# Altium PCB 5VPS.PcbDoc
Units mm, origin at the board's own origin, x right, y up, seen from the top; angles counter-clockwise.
Board outline 33.7 x 23.2 mm, 2 copper layers (Top Layer, Bottom Layer), stack 1.575 mm thick; 29 components, 18 nets, 69 pads, 4 vias.
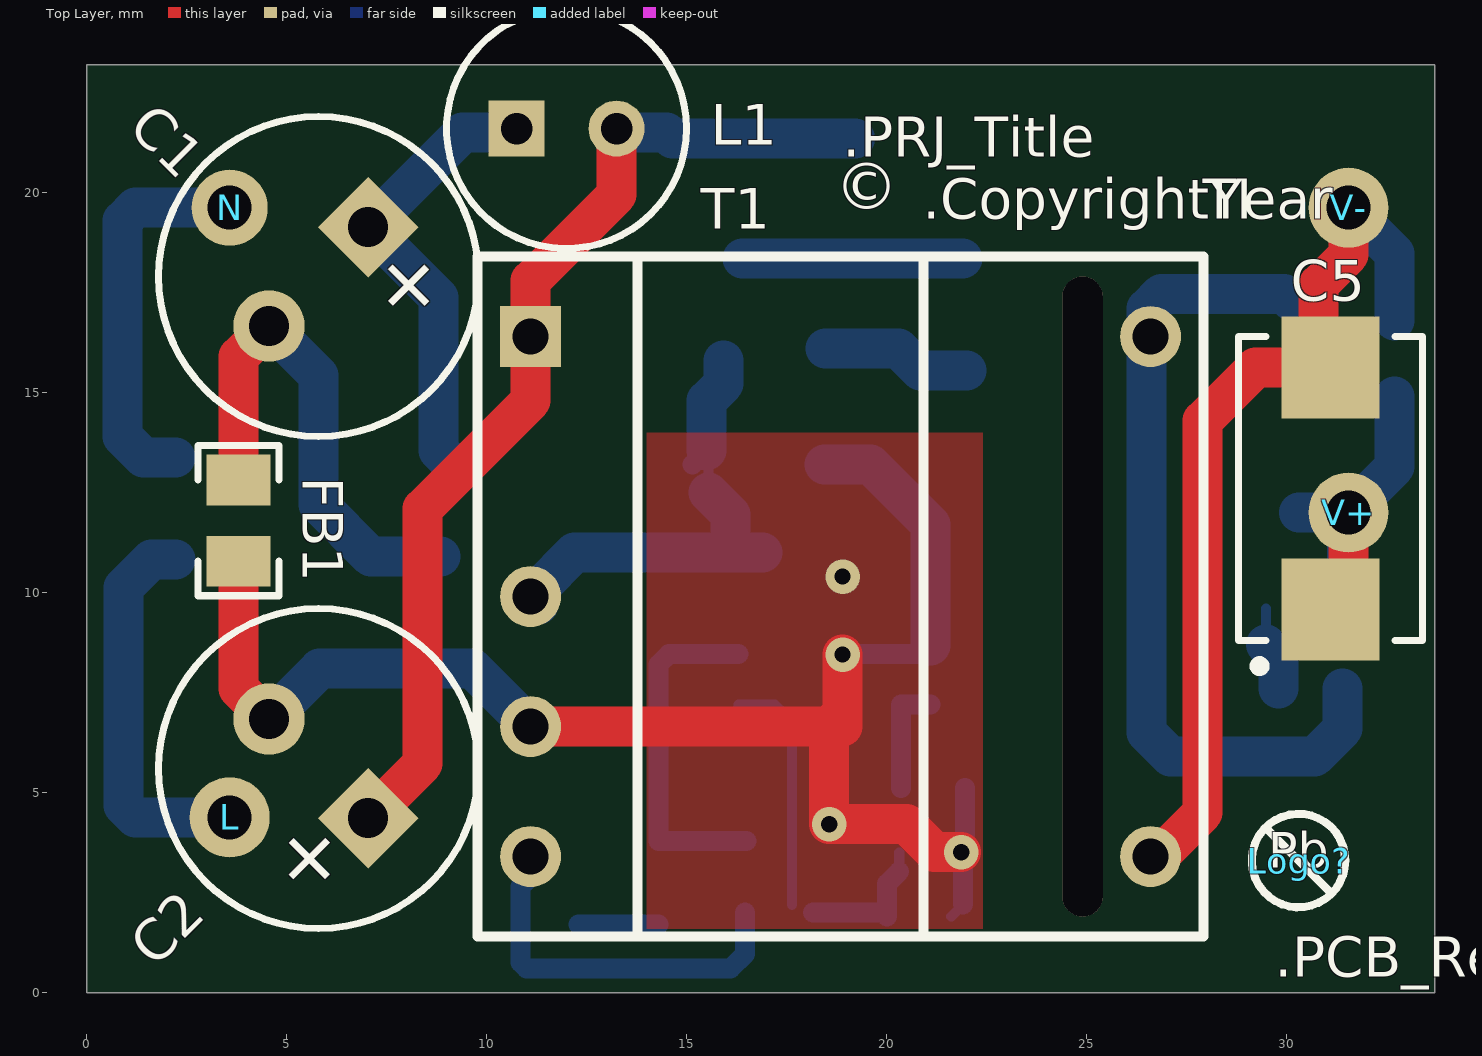
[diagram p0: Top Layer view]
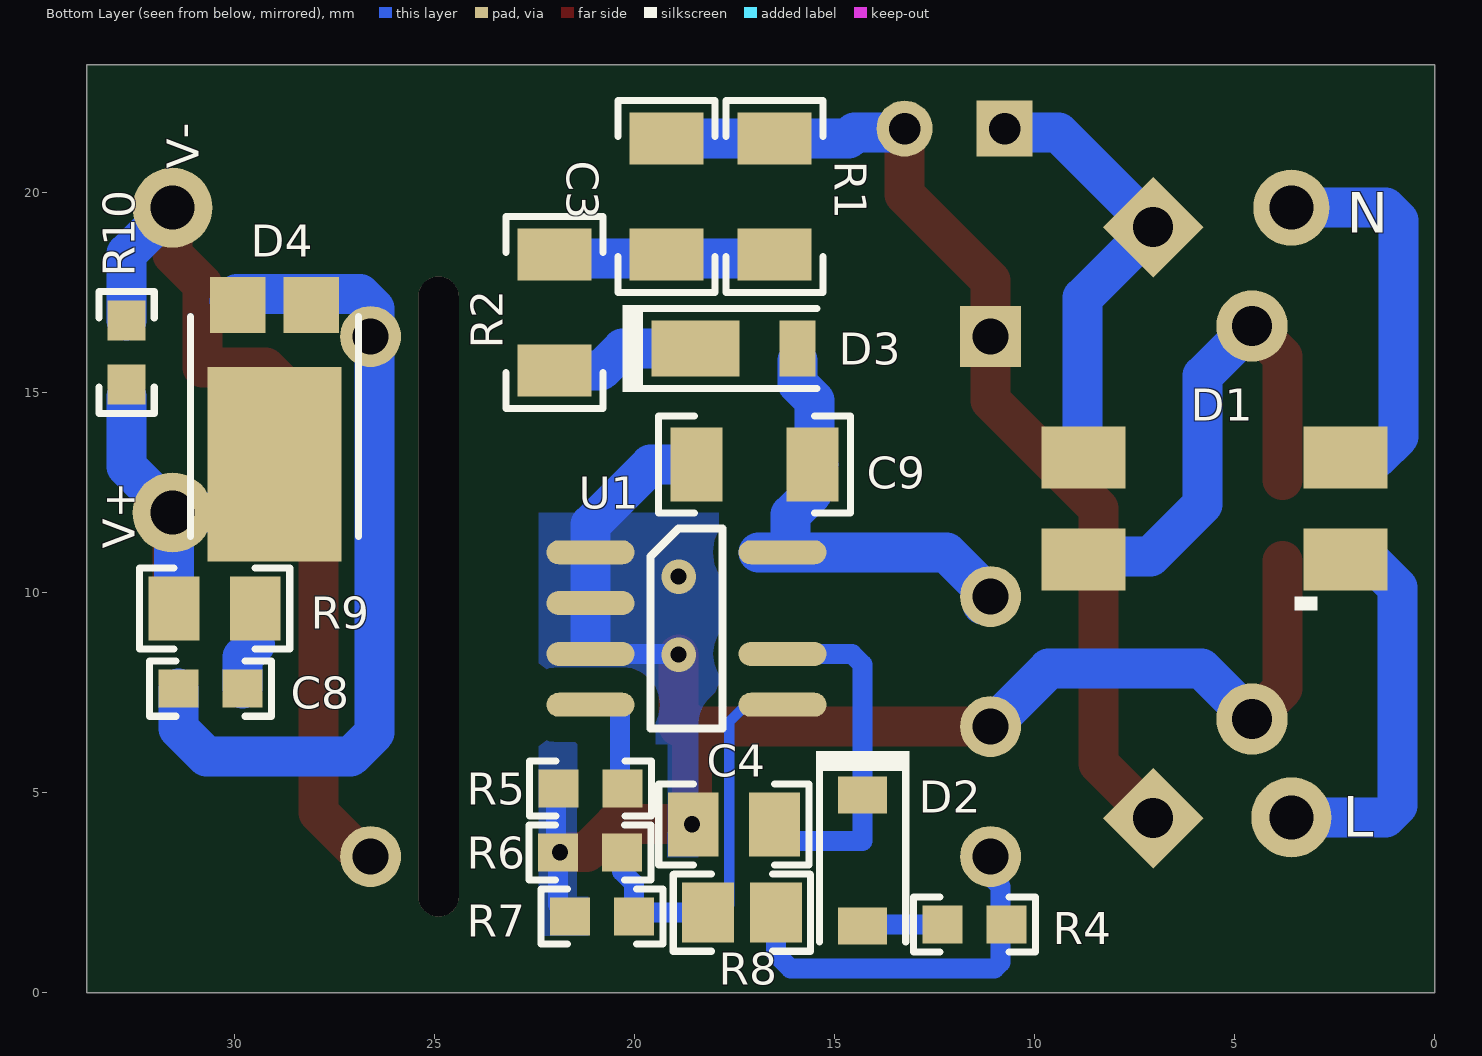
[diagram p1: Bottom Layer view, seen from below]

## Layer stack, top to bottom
Top Solder: solder mask 0.0102, Solder Resist, Dk 3.5
Top Layer: signal copper 0.0356
Dielectric1: core 1.5037, FR-4, Dk 4.8
Bottom Layer: signal copper 0.0356
Bottom Solder: solder mask 0.0102, Solder Resist, Dk 3.5

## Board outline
0,0 33.7,0 33.7,23.2 0,23.2

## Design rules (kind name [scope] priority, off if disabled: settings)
AcuteAngle [All] p1: minimum=4.50000000000000E+0001 checktracksonly=FALSE
AssemblyTestPointUsage [All] p1: valid=2
Clearance Clearance_BoardEdge_MountingHoles [OnCopper and InComponentClass('Mounting Holes') vs IsKeepOut] p1: gap=1.016
Clearance Clearance_BoardEdge_Poly [OnCopper and InPoly vs IsKeepOut] p2: gap=0.635
Clearance Clearance_BoardEdge [OnCopper and Not InComponentClass('Logo') and not InComponentClass('FiducialMark') and not InRegion(1000,500,4000,800) and Not IsKeepout vs IsKeepOut] p3: gap=1.905
Clearance Clearance_Poly [InPolygon] p4: gap=0.635
Clearance [All] p5: gap=0.203
ComponentClearance ComponentClearance_Shunt [InComponentClass('Header') vs InComponentClass('Shunt')] p1: gap=0 collisioncheckmode=3 verticalgap=0 showdistances=FALSE
ComponentClearance ComponentClearance_Logo [InComponentClass('Logo')] p2: gap=1.27 collisioncheckmode=3 verticalgap=0.254 showdistances=FALSE
ComponentClearance ComponentClearance_ScrewToNut [(HasFootprint('NY PMS 440 0025 PH')) vs (HasFootprint('Keystone_1902C'))] p3: gap=0.127 collisioncheckmode=3 verticalgap=0.254 showdistances=FALSE
ComponentClearance ComponentClearance_MountingHoles [InComponentClass('Mounting Holes')] p4: gap=6.35 collisioncheckmode=3 verticalgap=2540 showdistances=FALSE
ComponentClearance ComponentClearance_SmallPassives [HasFootprint('0201*') or HasFootprint('0402*') or HasFootprint('0508') or HasFootprint('0603*') or HasFootprint('0612') or HasFootprint('0805*') or HasFootprint('0815*') or HasFootprint('0830*') or HasFootprint('1206*') or HasFootprint('1210*') or HasFootprint('1808*') or HasFootprint('1812*') or HasFootprint('1825*') or HasFootprint('2010*') or HasFootprint('2220*') or HasFootprint('2225*') or HasFootprint('2512*') or HasFootprint('2728*') or HasFootprint('3518*') vs HasFootprint('0201*') or HasFootprint('0402*') or HasFootprint('0508') or HasFootprint('0603*') or HasFootprint('0612') or HasFootprint('0805*') or HasFootprint('0815*') or HasFootprint('0830*') or HasFootprint('1206*') or HasFootprint('1210*') or HasFootprint('1808*') or HasFootprint('1812*') or HasFootprint('1825*') or HasFootprint('2010*') or HasFootprint('2220*') or HasFootprint('2225*') or HasFootprint('2512*') or HasFootprint('2728*') or HasFootprint('3518*')] p5: gap=0.508 collisioncheckmode=3 verticalgap=0.254 showdistances=FALSE
ComponentClearance ComponentClearance_THtoSMT [IsThruComponent vs IsSMTComponent] p6: gap=2.54 collisioncheckmode=3 verticalgap=0.762 showdistances=FALSE
ComponentClearance ComponentClearance_THtoTH [IsThruComponent vs IsThruComponent] p7: gap=3 collisioncheckmode=3 verticalgap=0.762 showdistances=FALSE
ComponentClearance [All] p8: gap=1.016 collisioncheckmode=3 verticalgap=0.254 showdistances=FALSE
DiffPairsRouting [All] p1: maxlimit=2.54 minlimit=0.254 mostfreqgap=0.254 toplayer_minwidth=0.381 toplayer_maxwidth=0.381 toplayer_prefwidth=0.381 bottomlayer_minwidth=0.381 bottomlayer_maxwidth=0.381 bottomlayer_prefwidth=0.381 maxuncoupledlength=25.4
FabricationTestPointUsage TestPointUsage [All] p1: valid=2 allowmultiple=FALSE
FabricationTestpoint Testpoint [All] p1: side=3 testpointundercomponent=TRUE minsize=1.016 maxsize=2.54 preferedsize=1.524 minholesize=0 maxholesize=1.016 preferedholesize=0.813 testpointgrid=0.025 allowsidetop=TRUE allowsidebottom=TRUE usegrid=TRUE gridtolerance=0
FanoutControl Fanout_LCC [IsLCC] p1: bgadir=Out bgaviamode=Centered fanoutstyle=Auto fanoutdirection=Alternating viagrid=0.025 // Fanout_LCC (Default Rule)
FanoutControl Fanout_BGA [IsBGA] p2: bgadir=Out bgaviamode=Centered fanoutstyle=Auto fanoutdirection=Alternating viagrid=0.025 // Fanout_BGA (Default Rule)
FanoutControl Fanout_Default [All] p4: bgadir=Out bgaviamode=Centered fanoutstyle=Auto fanoutdirection=Alternating viagrid=0.025 // Fanout_Default (Default Rule)
FanoutControl Fanout_Small [(CompPinCount < 5)] p5: bgadir=Out bgaviamode=Centered fanoutstyle=Auto fanoutdirection=OutThenIn viagrid=0.025 // Fanout_Small (Default Rule)
HoleSize [All] p1: absolutevalues=TRUE maxlimit=6.375 minlimit=0.203 maxpercent=80.000 minpercent=20.000
MinimumAnnularRing MinimumAnnularRing_ThermalPadVias [IsVia and InAnyComponent] p1: minimumring=0.15
MinimumAnnularRing [All] p2: minimumring=0.229
MinimumSolderMaskSliver MinimumSolderMaskSliver_Logo [InComponentClass('Logo') vs InComponentClass('Logo')] p1: minsoldermaskwidth=0.018
MinimumSolderMaskSliver [All] p2: minsoldermaskwidth=0.1
PlaneClearance [All] p1: clearance=0.127
PlaneConnect [All] p1: planeconnectstyle=Direct reliefexpansion=0.254 reliefentries=4 reliefconductorwidth=0.254 reliefairgap=0.254
PolygonConnect [All] p1: connectstyle=Direct reliefconductorwidth=0.254 reliefentries=4 polygonreliefangle="90 Angle" airgapwidth=0.254
RoutingVias ThermalPadVias [IsVia and InAnyComponent] p1: holewidth=0.2 width=0.5 viastyle="Through Hole" minholewidth=0.2 minwidth=0.5 maxholewidth=0.33 maxwidth=0.6
RoutingVias [All] p2: holewidth=0.406 width=0.864 viastyle="Through Hole" minholewidth=0.2 minwidth=0.66 maxholewidth=1.016 maxwidth=1.651
SMDToCorner [All] p1: distance=30000
SilkToSilkClearance [All] p1: silktosilkclearance=0.127
SilkToSolderMaskClearance SilkscreenOverComponentPads [IsPad] p1: minsilkscreentomaskgap=0.127 clearancetoexposedcopper=TRUE
SolderMaskExpansion [All] p1: expansion=0.05
UnpouredPolygon [All] p1: allowunpoured=FALSE
Width [All] p1: maxlimit=2.54 minlimit=0.152 preferedwidth=0.254 checkconnectedcopper=TRUE
14 further rules are at their usual default settings.

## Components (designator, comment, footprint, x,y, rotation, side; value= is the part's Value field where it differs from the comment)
C1 "400AX8.2M8X16" CAPPRD350W60D800H1100 5.8,17.9 r225 top
C2 "400AX8.2M8X16" CAPPRD350W60D800H1100 5.8,5.6 r135 top
C3 "GRM31A7U2J221JW31D" 1206 19.2,19.9 r270 bottom
C4 "GRM21BC81E475KA12L" 0805_HV 17.516,4.2 r0 bottom
C5 "TPSE477K010R0045" 7343-43 31.1,12.6 r90 top
C8 "C1608C0G1H102J" 0603 30.6,7.6 r0 bottom
C9 "GRM31A7U3A330JW31D" 1206 17,13.2 r0 bottom
D1 "MB6S" TO-269AA 5.5,12.1 r0 bottom
D2 "BAV21W-7-F" SOD-123 14.3,3.3 r270 bottom
D3 "DFLR1600" powerDI123 17.2,16.1 r180 bottom
D4 "PDS1040L-13" PowerDI5 29,15.2 r270 bottom
FB1 "MPZ2012S601A" 0805_HV 3.8,11.8 r270 top
L "KEY1050-ND" TESTPOINT#1 2.7,19.3 r90 top
L1 "470uH" IND_WE-TI_XS 12,21.6 r0 top
Logo? "Pb-Free Symbol" Pb-Free_Overlay_Small 30.3,3.3 r0 top
N "KEY1050-ND" TESTPOINT#2 2.7,3.4 r90 top
R1 "RC1206FR-07300KL" 1206 16.5,19.9 r270 bottom
R2 "RC1206FR-07300RL" 1206 22,17 r90 bottom
R4 "CRCW060322R0JNEA" 0603 11.5,1.7 r180 bottom
R5 "RC0603JR-071K3L" 0603 21.1,5.1 r180 bottom
R6 "CRCW060336K0JNEA" 0603 21.116,3.5 r180 bottom
R7 "CRCW0603910KJNEA" 0603 20.816,1.9 r180 bottom
R8 "CRCW080562K0JNEA" 0805 17.316,2 r180 bottom
R9 "ERJ-6GEYJ150V" 0805_HV 30.5,9.6 r0 bottom
R10 "RC0603JR-073K9L" 0603 32.7,16 r270 bottom
T1 "TF-1613(EE-16)" TF-1613(EE-16) 18.85,9.9 r0 top
U1 "UCC28910D" D0007A_N 18.7,9.1 r180 bottom
V+ "KEY1050-ND" TESTPOINT#3 32.4,10.4 r0 top
V- "KEY1050-ND" TESTPOINT#4 31.8,19.4 r0 top

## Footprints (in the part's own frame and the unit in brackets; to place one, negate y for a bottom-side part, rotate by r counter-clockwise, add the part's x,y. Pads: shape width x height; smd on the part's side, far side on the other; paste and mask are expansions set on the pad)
0603 [mm] "0603 from SM-752 data"
  rect 1x0.95 smd: 1(-0.8,0) 2(0.8,0)
  silkscreen extent -1.52,-0.69 1.52,0.69, body extent -0.87,-0.47 0.87,0.47, height 0.85
0805 [mm] "0805 from SM-752 data"
  rect 1.3x1.5 smd: 1(-0.85,0) 2(0.85,0)
  silkscreen extent -1.72,-0.97 1.72,0.97, body extent -1.1,-0.72 1.1,0.72, height 1.1
0805_HV [mil] "0805 with 30mil clearance between pads"
  rect 50x63 smd: 1(-40,0) 2(40,0)
  silkscreen extent -74,-40 74,40, body extent -43,-29 43,29, height 43
1206 [mm] "1206 from SM-752 data"
  rect 1.3x1.85 smd: 1(-1.45,0) 2(1.45,0)
  silkscreen extent -2.4,-1.21 2.4,1.21, body extent -1.7,-0.9 1.7,0.9, height 1.35
7343-43 [mm] "Medium density IPC based on Kemet T495 series"
  rect 2.55x2.45 smd: 1(-3.025,0) 2(3.025,0)
  silkscreen extent -4.56,-2.3 3.8,2.3, body extent -3.8,-2.3 3.8,2.3, height 4.3
CAPPRD350W60D800H1100 [mm] "Capacitor, Alum, 8x11mm"
  rect 1.78x1.78 hole 1: 1(-1.75,0)
  round 1.78 hole 1: 2(1.75,0)
  silkscreen extent -4,-4 4,4, body extent -4.03,-4.03 4.03,4.02, height 11.79
D0007A_N [mm] "SOIC, 7-Leads, Body 4.9x3.9mm, Pitch 1.27mm, IPC Medium Density"
  oval 2.2x0.6 smd: 1(-2.4,1.905) 2(-2.4,0.635) 3(-2.4,-0.635) 4(-2.4,-1.905) 5(2.4,-1.905) 6(2.4,-0.635) 8(2.4,1.905)
  silkscreen extent -0.9,-2.5 0.9,2.5, body extent -3,-2.5 3,2.5, height 1.54
IND_WE-TI_XS [mm] "Wurth WE-TI 5075"
  rect 1.4x1.4 hole 0.787: 1(-1.25,0)
  round 1.4 hole 0.787: 2(1.25,0)
  silkscreen extent -3,-3 3,3, body extent -3.01,-3.01 3.01,3.01, height 8.5
Pb-Free_Overlay_Small [mm]
  silkscreen extent -1.16,-1.17 1.17,1.17
PowerDI5 [mm] "Diodes Inc recommended land pattern, ap02001.pdf rev 60"
  rect 1.4x1.39 smd: 1(-1.991,0.92) 2(-1.991,-0.92)
  rect 4.86x3.36 smd: 3(1.991,0)
  silkscreen extent -1.7,-2.1 3.8,2.1, body extent -2.27,-2.02 4.33,2.03, height 1.17
powerDI123 [mm] "Diodes Inc recommended land pattern, document number DS30628 Rev. 6-2"
  rect 2.2x1.4 smd: 1(-1.275,0)
  rect 0.9x1.4 smd: 2(1.275,0)
  silkscreen extent -3.1,-1.09 1.76,1.09, body extent -2.37,-0.96 1.53,0.97, height 1
SOD-123 [mm] "On Semi recommended land pattern"
  rect 0.915x1.22 smd: 1(-1.637,0) 2(1.637,0)
  silkscreen extent -2.74,-1.17 2.03,1.17, body extent -1.93,-0.9 1.93,0.9, height 1.35
TESTPOINT#1 [mm]
  round 2 hole 1.1: 1(-14.92,-0.88)
TESTPOINT#2 [mm]
  round 1.9 hole 1.1: 1(16.22,-0.88)
TESTPOINT#3 [mm]
  round 2 hole 1.1: 1(-0.85,1.6)
TESTPOINT#4 [mm]
  round 2 hole 1.1: 1(-0.25,0.22)
TF-1613(EE-16) [mm]
  rect 1.524x1.524 hole 0.9: 1(-7.75,6.5)
  round 0 all layers, no hole: 2(-7.75,3.25) 7(7.75,-3.25) 8(7.75,0) 9(7.75,3.25)
  round 1.524 hole 0.9: 3(-7.75,0) 4(-7.75,-3.25) 5(-7.75,-6.5) 6(7.75,-6.5) 10(7.75,6.5)
  silkscreen extent -9.08,-8.5 9.08,8.5, body extent -9.1,-8.5 9,8.5, height 10.96
TO-269AA [mm] "Fairchild"
  rect 2.1x1.55 smd: 1(-3.28,1.27) 2(-3.28,-1.27) 3(3.28,-1.27) 4(3.28,1.27)
  silkscreen extent -2.58,2.2 -2,2.55, body extent -3.5,-2.47 3.5,2.47, height 2.91

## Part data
C1 C2: library part 400AX6R8M8x11, "CAP, AL, 6.8uF, 400V, +/-20%, TH"
C3: "CAP, CERM, 220pF, 630V, +/-5%, U2J, 1206"
C4: "CAP, CERM, 4.7uF, 25V, +/-10%, X6S, 0805"
C5: "CAP, TA, 470uF, 10V, +/-10%, 0.045 ohm, SMD"
C8: "CAP, CERM, 1000pF, 50V, +/-5%, C0G/NP0, 0603"
C9: library part GRM31A7U3A331JW31D, "CAP, CERM, 33pF, 1000V, +/-5%, U2J, 1206"
D1: library part MB1S, "Diode, Switching-Bridge, 100V, 0.5A, SOIC-4"
D2: "Diode, Switching, 200V, 0.2A, SOD-123"
D3: library part DFLU1400-7, "Diode, Superfast Rectifier, 600V, 1A, PowerDI123"
D4: "Diode, Schottky, 40V, 10A, PowerDI5"
FB1: "2A Ferrite Bead, 600 ohm @ 100MHz, SMD"
L N V+ V-: library part TESTPOINT, "TEST POINT.  No entry in BOM."
L1: library part 7447462471, "Inductor, Unshielded Drum Core, Ferrite, 470uH, 0.35A, 1.58 ohm, TH"
Logo?: library part Pb-Free
R1: "RES, 300k ohm, 1%, 0.25W, 1206"
R2: "RES, 300 ohm, 1%, 0.25W, 1206"
R4: "RES, 22 ohm, 5%, 0.1W, 0603"
R5: "RES, 1.3k ohm, 5%, 0.1W, 0603"
R6: "RES, 36k ohm, 5%, 0.1W, 0603"
R7: "RES, 910k ohm, 5%, 0.1W, 0603"
R8: "RES, 62k ohm, 5%, 0.125W, 0805"
R9: "RES, 15 ohm, 5%, 0.125W, 0805"
R10: "RES, 3.9k ohm, 5%, 0.1W, 0603"
U1: "LOW STAND-BY POWER, CV / CC PWM HV SWITCHER WITH PRIMARY SIDE REGULATION, D0007A"

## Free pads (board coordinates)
  oval 1x16 hole 1 slot 16 at 90 deg unplated: 0(24.9,9.9)

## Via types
v1: diameter 0.864, hole 0.406, Top Layer to Bottom Layer, 4 vias

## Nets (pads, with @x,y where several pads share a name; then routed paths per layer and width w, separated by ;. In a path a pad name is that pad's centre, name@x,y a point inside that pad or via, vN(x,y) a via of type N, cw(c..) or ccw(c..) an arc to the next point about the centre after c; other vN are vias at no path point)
GND: C2.2 C4.2 C9.2 FB1.2 R5.1 R6.1 R7.1 T1.4 U1.1 U1.2 U1.3 | length 39.5
  Top Layer w1: FB1.2 3.8,7.6 C2.2 ; T1.4@11.6,6.65 18.55,6.65 ; 18.8,6.9 18.566,6.666 18.566,6.65 ; v1(18.9,8.45) 18.9,6.65 18.566,6.65 ; v1(21.866,3.51) 21.2,3.51 20.5,4.21 v1(18.566,4.21) 18.566,6.65
  Bottom Layer w0.254: C4.2@18.336,4.396 C4.2 18.556,4.2 v1(18.566,4.21) ; R7.1 R7.1@21.916,2.2
  Bottom Layer w0.5: v1@18.915,8.465 U1.3 ; R7.1@21.916,2.2 R6.1 ; R6.1@21.966,3.55 R5.1@21.966,5.11
  Bottom Layer w1: C2.2 5.825,8.1 9.65,8.1 T1.4 ; C9.2 19.6,13.2 21.1,11.7 U1.2 U1.3@21.1,8.67
  other v1: 18.9,10.4
NetC1_1: C1.1 D1.3 L1.1 | length 11.3
  Bottom Layer w1: D1.3@8.98,13.37 8.8,13.55 8.8,17.375 C1.1 9.4,21.5 L1.1@10.75,21.5
NetC1_2: C1.2 D1.4 FB1.1 | length 12.7
  Top Layer w1: FB1.1 3.8,15.9 C1.2
  Bottom Layer w1: C1.2 5.8,15.425 5.8,12.207 7.107,10.9 D1.4@8.85,10.9
NetC2_1: C2.1 C3.1 L1.2 R1.1 T1.1 | length 25.7
  Top Layer w1: C2.1 8.4,5.725 8.4,12.1 11.1,14.8 11.1,17.8 13.25,19.95 L1.2@13.25,21.5
  Bottom Layer w1: L1.2@13.25,21.5 14.5,21.5 14.65,21.35 C3.1@19.21,21.35
NetC3_2: C3.2 R1.2 R2.2 | length 5.5
  Bottom Layer w1: R1.2@16.4,18.35 R2.2@21.9,18.35
NetC4_1: C4.1 D2.1 U1.6 | length 8.7
  Bottom Layer w0.5: U1.6 14.565,8.465 14.3,8.2 14.3,3.79 C4.1@16.5,3.79
NetC5_1: C5.1 D4.3 R9.2 R10.2 V+.1 | length 8.7
  Top Layer w1: C5.1@31.55,10.325 V+.1
  Bottom Layer w1: D4.3@30.309,12 V+.1 32.7,13.15 R10.2@32.7,14.9 ; R9.2 V+.1@31.516,11.966
NetC5_2: C5.2 R10.1 T1.6 V-.1 | length 22.5
  Top Layer w1: T1.6@26.7,3.3 27.9,4.5 27.9,14.3 29.225,15.625 30.8,15.625 30.8,17.7 31.55,18.45 V-.1
  Bottom Layer w1: V-.1 32.7,18.47 R10.1
NetC8_1: C8.1 R9.1 | length 2.1
  Bottom Layer w0.254: 29.484,8.7 R9.1
  Bottom Layer w1: 29.484,8.7 29.8,8.384 C8.1
NetC8_2: C8.2 D4.1 D4.2 T1.10 | length 20.9
  Bottom Layer w1: D4.2@30.12,17.291 29.942,17.469 26.869,17.469 26.5,17.1 26.5,6.5 27.1,5.9 30.7,5.9 31.4,6.6 C8.2
NetC9_1: C9.1 D3.2 T1.3 U1.8 | length 11.8
  Bottom Layer w0.254: C9.1@15.55,12.5 C9.1
  Bottom Layer w0.5: C9.1@15.15,13.2 C9.1@15.5,13.55
  Bottom Layer w1: T1.3@11.3,9.7 11.3,10.1 12.205,11.005 U1.8@16.9,11.005 ; C9.1@15.5,13.55 15.5,14.8 15.925,15.225 D3.2@15.925,15.8 ; C9.1@15.55,12.5 16.1,11.95 16.1,11.205 U1.8
NetD1_1: D1.1 L.1 | length 9.8
  Bottom Layer w1: D1.1 1.63,10.83 0.92,10.12 0.92,4.68 1.22,4.38 L.1
NetD1_2: D1.2 N.1 | length 9.8
  Bottom Layer w1: D1.2 1.43,13.37 0.9,13.9 0.9,19.3 1.22,19.62 N.1
NetD2_2: D2.2 R4.1 | length 2
  Bottom Layer w0.5: R4.1@12.3,1.7 D2.2@14.3,1.7
NetD3_1: D3.1 R2.1 | length 3.8
  Bottom Layer w1: D3.1 20.3,16.1 20.85,15.55 R2.1
NetR4_2: R4.2 R8.2 T1.5 | length 9.8
  Bottom Layer w0.5: T1.5@11.6,3.4 10.853,2.653 10.853,2.105 10.85,2.102 10.85,0.75 11,0.6 16.1,0.6 16.466,0.966 R8.2
NetR5_2: R5.2 U1.4 | length 2.8
  Bottom Layer w0.5: R5.2@20.366,5.11 20.366,7.205 21.09,7.205 U1.4
NetR6_2: R6.2 R7.2 R8.1 U1.5 | length 9.7
  Bottom Layer w0.254: U1.5 17.205,7.195 17.633,6.767 R8.1@17.633,2.189 ; R7.2@19.916,2 R7.2 ; R6.2@20.316,3.025 R6.2
  Bottom Layer w0.5: R8.1 R7.2@19.916,2 ; R7.2 20.016,2.725 R6.2@20.316,3.025
pads on no net: T1.2 T1.7 T1.8 T1.9

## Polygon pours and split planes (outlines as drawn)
GND on Top Layer "Top Layer-No Net" (solid, remove dead copper, pour order 2): 14,14 22.4,14 22.4,1.6 14,1.6 14,14
GND on Bottom Layer "Bottom Layer-No Net" (solid, remove dead copper, pour order 4): 17.9,12 22.4,12 22.4,1.426 17.9,1.426 17.9,12

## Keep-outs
Keep-Out Layer:
  text ".Layer_Name" at 14.656,-21.806 h1.52

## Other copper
Top Layer:
  text ".PRJ_Number" at 39.9,17.03 h1
  text ".Layer_Name" at 14.656,-21.806 h1.52
Bottom Layer:
  text ".PRJ_Number" at 39.9,15.157 h1
  text ".Layer_Name" at 14.656,-21.806 h1.52

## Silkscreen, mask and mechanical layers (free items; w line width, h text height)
Top Overlay:
  text ".PRJ_Number" at 39.9,22.65 h1
  text ".PRJ_Title" at 18.9,20.9 h1
  text ".CopyrightYear" at 20.9,19.35 h1
  text "TI" at 27.91,19.35 h1
  text "©" at 18.7,19.2 h2
  text ".PCB_Rev" at 29.7,0.4 h1
  text ".Layer_Name" at 14.656,-21.806 h1.52
Bottom Overlay:
  text ".PRJ_Number" at 39.9,9.537 h1
  text ".Layer_Name" at 14.656,-21.806 h1.52
Top Paste:
  text ".PRJ_Number" at 39.9,18.904 h1
  text ".Layer_Name" at 14.656,-21.806 h1.52
Bottom Paste:
  text ".PRJ_Number" at 39.9,13.284 h1
  text ".Layer_Name" at 14.656,-21.806 h1.52
Top Solder:
  text ".PRJ_Number" at 39.9,20.777 h1
  text ".Layer_Name" at 14.656,-21.806 h1.52
  text ".Layer_Name" at 14.656,-21.806 h1.52
Bottom Solder:
  text ".PRJ_Number" at 39.9,11.411 h1
  text ".Layer_Name" at 14.656,-21.806 h1.52
Drill Guide:
  text ".PRJ_Number" at 39.9,0.171 h1
  text ".Layer_Name" at 14.656,-21.806 h1.52
M1 Board Outline:
  the board outline again, w0.254
  text ".PRJ_Number" at 39.9,7.664 h1
  text ".Layer_Name" at 14.656,-21.806 h1.52
M2 Board Dimensions:
  rectangle: -0.013,-7.252 3.162,-4.077
  rectangle: 3.162,-10.427 12.687,-7.252
  lines w0.178: -0.013,-7.252 25.387,-7.252 ; 3.162,-10.427 3.162,-4.077 ; 6.337,-10.427 6.337,-4.077 ; 12.687,-10.427 12.687,-4.077 ; 19.037,-10.427 19.037,-4.077 ; -0.013,-10.427 25.387,-10.427 25.387,-4.077 -0.013,-4.077 -0.013,-10.427
  lines w0.254: -0.013,-12.078 -0.013,-11.57 ; 1.511,-12.332 -0.013,-11.824 ; 1.511,-11.316 -0.013,-11.824 ; 6.187,-11.824 -0.013,-11.824 ; 19.188,-11.824 25.387,-11.824 ; 23.863,-12.332 25.387,-11.824 ; 23.863,-11.316 25.387,-11.824 ; 25.387,-12.078 25.387,-11.57
  text ".PRJ_Number" at 39.9,5.791 h1
  text "25.4 (mm)" at 6.441,-12.738 h1.52
  text ".Layer_Name" at 14.656,-21.806 h1.52
M3 3D STEP Top:
  text ".Layer_Name" at 14.656,-21.806 h1.52
M4 3D STEP Bottom:
  text ".Layer_Name" at 14.656,-21.806 h1.52
M5 Assembly Top:
  lines w0.254: -7.417,-23.626 160.223,-23.626 ; -7.417,-18.462 160.274,-18.462 ; -7.417,-13.297 -7.417,-28.791 94.31,-28.791 160.274,-28.791 160.274,-13.297 -7.404,-13.297 -7.404,-28.791 32.614,-28.791 ; 55.194,-28.791 55.194,-13.297 ; 87.376,-18.462 87.376,-13.297 ; 108.712,-18.462 108.712,-13.297 ; 124.511,-28.956 124.511,-23.804
  text ".PRJ_Number" at 39.9,3.918 h1
  text "COMPONENTS MARKED 'DNP' SHOULD NOT BE POPULATED." at 29.299,-8.09 h1.52
  text "ASSEMBLY VARIANT:" at 29.286,-11.024 h1.52
  text ".VariantName" at 55.601,-11.024 h1.52
  text "PCB VIEWED FROM TOP SIDE" at -5.804,-16.654 h1.52
  text "BOARD #:" at 57.099,-16.654 h1.52
  text ".PRJ_Number" at 70.955,-16.654 h1.52
  text "REV:" at 92.405,-16.654 h1.52
  text ".PCB_Rev" at 99.809,-16.654 h1.52
  text "SVN REV:" at 113.69,-16.654 h1.52
  text ".VersionControl_RevNumber" at 126.543,-16.654 h1.52
  text "IGNORE ->" at -5.804,-21.806 h1.52
  text "PLOT NAME =" at -5.804,-27.034 h1.52
  text ".plot_File_Name" at 14.656,-27.034 h1.52
  text "GENERATED    :" at 57.15,-27.034 h1.52
  text ".Print_Date" at 79.235,-27.034 h1.52
  text ".Print_Time" at 97.752,-27.034 h1.52
  text "TEXAS INSTRUMENTS" at 129.87,-27.034 h1.52
M6 Assembly Bottom:
  lines w0.254: -7.429,-18.474 160.261,-18.474 ; -7.379,-23.639 160.261,-23.639 ; 28.334,-28.969 28.334,-23.817 ; 44.133,-18.474 44.133,-13.31 ; 65.468,-18.474 65.468,-13.31 ; 97.65,-28.804 97.65,-13.31 ; 120.231,-28.804 160.249,-28.804 160.249,-13.31 -7.429,-13.31 -7.429,-28.804 58.534,-28.804 160.261,-28.804 160.261,-13.31
  text ".PRJ_Number" at 39.9,2.045 h1
  text "COMPONENTS MARKED 'DNP' SHOULD NOT BE POPULATED." at 154.991,-8.077 h1.52
  text ".VariantName" at 128.473,-11.024 h1.52
  text "ASSEMBLY VARIANT:" at 154.864,-11.024 h1.52
  text ".VersionControl_RevNumber" at 26.302,-16.667 h1.52
  text "SVN REV:" at 39.154,-16.667 h1.52
  text ".PCB_Rev" at 53.035,-16.667 h1.52
  text "REV:" at 60.439,-16.667 h1.52
  text ".PRJ_Number" at 81.89,-16.667 h1.52
  text "BOARD #:" at 95.745,-16.667 h1.52
  text "PCB VIEWED FROM BOTTOM SIDE" at 158.648,-16.667 h1.52
  text "IGNORE ->" at 64.715,-21.806 h1.52
  text "TEXAS INSTRUMENTS" at 22.974,-27.047 h1.52
  text ".Print_Time" at 55.093,-27.047 h1.52
  text ".Print_Date" at 73.609,-27.047 h1.52
  text "GENERATED    :" at 95.694,-27.047 h1.52
  text ".plot_File_Name" at 138.189,-27.047 h1.52
  text "PLOT NAME =" at 158.648,-27.047 h1.52
M9 Title Sheet:
  drawing of 57 lines, arcs and shapes, not listed
  text "1" at 18.792,204.127 h1.78
  text "2" at 82.182,204.127 h1.78
  text "3" at 145.411,204.127 h1.78
  text "4" at 209.08,204.127 h1.78
  text "5" at 272.555,204.127 h1.78
  text "6" at 336.182,204.127 h1.78
  text "A" at -10.579,175.095 h1.78
  text "A" at 365.341,175.095 h1.78
  text "B" at -10.579,114.643 h1.78
  text "B" at 365.341,114.643 h1.78
  text "C" at -10.579,54.318 h1.78
  text "C" at 365.341,54.318 h1.78
  text "PROJECT TITLE:" at 288.125,7.048 h1.14
  text ".PRJ_Title" at 289.395,3.662 h1.78
  text "DESIGNED FOR:" at 288.125,-0.597 h1.14
  text ".PRJ_Customer" at 289.395,-4.153 h1.78
  text "D" at -10.579,-5.88 h1.78
  text "D" at 365.341,-5.88 h1.78
  text "FILE NAME:" at 288.125,-8.217 h1.14
  text ".PCB_File_Name_No_Path" at 289.395,-11.265 h1.78
  text "Texas Instruments (TI) and/or its licensors do not warrant the accuracy or completeness of this specification" at 161.9,-15.376 h1.14
  text "ENGINEER:" at 288.125,-15.583 h1.14
  text "LAYOUT BY:" at 326.352,-15.583 h1.14
  text "or any information contained therein. TI and/or its licensors do not warrant that this design will meet" at 160.757,-18.237 h1.14
  text ".PRJ_Engineer" at 289.395,-19.52 h1.78
  text ".PCB_Layout" at 327.635,-19.52 h1.78
  text "the specifications, will be suitable for your application or fit for any particular purpose, or will operate in" at 160.757,-21.099 h1.14
  text ".Layer_Name" at 14.656,-21.806 h1.52
  text "ALTIUM DESIGNER VERSION:" at 326.352,-23.457 h1.14
  text "an implementation. TI and/or its licensors do not warrant that the design is production worthy. You should" at 160.757,-23.961 h1.14
  text "completely validate and test your design implementation to confirm the system functionality for your application." at 161.9,-26.822 h1.14
  text ".print_Scale" at 289.395,-26.843 h1.78
  text ".Application_BuildNumber" at 327.635,-26.843 h1.78
  text "1" at 18.792,-32.093 h1.78
  text "2" at 82.182,-32.093 h1.78
  text "3" at 145.411,-32.093 h1.78
  text "4" at 209.08,-32.093 h1.78
  text "5" at 272.555,-32.093 h1.78
  text "6" at 336.182,-32.093 h1.78
M10 Fab Notes:
  drawing of 212 lines, arcs and shapes, not listed
  text "DESIGN INFORMATION" at 314.478,172.974 h1.52
  text "(REFER ALSO ARRAY/PANEL PROFILING INFORMATION)" at 305.294,168.866 h1.52
  text "BOARD SIZE" at 287.87,168.758 h1.52
  text "3450MIL" at 299.613,165.511 h1.52
  text "X" at 312.457,165.511 h1.52
  text "4950MIL" at 318.333,165.511 h1.52
  text "Number of Layers :" at 298.106,160.503 h1.52
  text "2" at 325.914,160.249 h1.52
  text "MIN. TRACK WIDTH:" at 298.106,156.972 h1.52
  text "8" at 325.951,156.972 h1.52
  text "MIL" at 329.881,156.972 h1.52
  text "MIN. CLEARANCE:" at 298.106,153.619 h1.52
  text "8" at 325.951,153.619 h1.52
  text "MIL" at 329.881,153.619 h1.52
  text "MIN. VIA PAD SIZE:" at 298.106,150.266 h1.52
  text "24" at 325.189,150.266 h1.52
  text "MIL" at 329.881,150.266 h1.52
  text "0.05mm (2MIL)" at 315.759,146.667 h1.52
  text "MINIMUM ANNULAR RING" at 289.744,146.558 h1.52
  text "EXTERNAL" at 333.742,146.558 h1.52
  text "PER" at 294.824,143.561 h1.52
  text "IPC-D-275 CLASS 2 LEVEL C" at 300.412,143.561 h1.52
  text "MIL, HOLES" at 338.213,140.709 h1.52
  text "+/-" at 328.244,140.691 h1.52
  text "+/-" at 349.936,140.691 h1.52
  text "REGISTRATION TOLERANCES:" at 289.744,140.564 h1.52
  text "METAL" at 320.218,140.564 h1.52
  text "5" at 334.853,140.564 h1.52
  text "3" at 356.012,140.564 h1.52
  text "MIL" at 358.964,140.564 h1.52
  text "MATERIAL:" at 287.844,135.243 h1.52
  text "FR-4 High Tg" at 312.9,131.679 h1.52
  text "FR-408" at 298.538,131.461 h1.52
  text "X" at 309.003,131.461 h1.52
  text "OTHER" at 336.333,131.461 h1.52
  text "62 MIL (1.6mm) +/-10%" at 306.668,127.328 h1.52
  text "THICKNESS:" at 289.744,127.219 h1.52
  text "X" at 303.413,127.219 h1.52
  text "OTHER" at 339.305,127.219 h1.52
  text "TOLERANCE:" at 289.744,123.206 h1.52
  text "X" at 311.062,123.206 h1.52
  text "ANSI IPC-6012 TYPE 3 CLASS 2" at 315.81,123.206 h1.52
  text "OTHER +/-" at 315.81,119.244 h1.52
  text "BOW & TWIST:" at 289.744,115.256 h1.52
  text "X" at 311.062,115.256 h1.52
  text "ANSI IPC-6012 TYPE 3 CLASS 2" at 315.81,115.256 h1.52
  text "OTHER +/-" at 315.81,111.23 h1.52
  text "COPPER THICKNESS (FINISHED):" at 287.844,107.788 h1.52
  text "1.4MIL (1oz)" at 310.196,103.909 h1.52
  text "2MIL (1.4oz)" at 329.678,103.909 h1.52
  text "2.8MIL (2oz)" at 348.144,103.909 h1.52
  text "OUTER:" at 296.912,103.801 h1.52
  text "X" at 306.934,103.784 h1.52
  text "1.4MIL (1oz)" at 310.196,99.922 h1.52
  text "2.8MIL (2oz)" at 329.678,99.922 h1.52
  text "N/A" at 348.132,99.931 h1.52
  text "INNER SIGNAL:" at 289.57,99.813 h1.52
  text "X" at 306.97,99.813 h1.52
  text "DRILLING:" at 287.844,96.282 h1.52
  text "REFERENCE:" at 289.744,93.31 h1.52
  text "X" at 306.209,93.31 h1.52
  text "AS SHOWN" at 310.958,93.31 h1.52
  text "X" at 329.094,93.31 h1.52
  text "NC_DRILL FILES" at 332.574,93.31 h1.52
  text "PTH MIN COPPER THICKNESS:" at 289.744,89.297 h1.52
  text "X" at 324.039,89.297 h1.52
  text "1MIL" at 327.519,89.297 h1.52
  text "OTHER" at 340.143,89.297 h1.52
  text "BOARD FINISH:" at 287.844,85.259 h1.52
  text "SILKSCREEN:" at 291.787,82.261 h1.52
  text "X" at 315.886,82.261 h1.52
  text "TOP" at 319.086,82.261 h1.52
  text "X" at 328.84,82.261 h1.52
  text "BOTTOM" at 332.066,82.261 h1.52
  text "SILKSCREEN COLOR:" at 291.787,78.02 h1.52
  text "X" at 315.86,78.02 h1.52
  text "WHITE" at 319.086,78.02 h1.52
  text "OTHER" at 332.066,78.02 h1.52
  text "SOLDER RESIST COLOR:" at 291.787,73.702 h1.52
  text "X" at 306.208,69.658 h1.52
  text "GREEN" at 309.434,69.658 h1.52
  text "BLUE" at 324.446,69.658 h1.52
  text "OTHER" at 338.111,69.658 h1.52
  text "IMMERSION GOLD (ENIG)" at 314.794,64.87 h1.52
  text "ENEPIG" at 348.767,64.786 h1.52
  text "SURFACE FINISH:" at 287.844,64.761 h1.52
  text "X" at 310.045,64.761 h1.52
  text "IMM. TIN/SILVER OR EQUIV" at 296.215,60.773 h1.52
  text "OTHER" at 332.574,60.773 h1.52
  text "ARRAY/PANEL:" at 287.844,56.226 h1.52
  text "CUT AND TRIM PER MECH LAYER 1" at 314.794,56.118 h1.52
  text "N.C. ROUTE" at 314.794,52.264 h1.52
  text "X" at 332.04,52.264 h1.52
  text "V. SCORE" at 336.79,52.264 h1.52
  text "CERTIFICATION:" at 287.844,48.784 h1.52
  text "MATERIALS AND WORKMANSHIP FOR ALL PCBS" at 306.259,48.784 h1.52
  text "TO MEET OR EXCEED THE REQUIREMENTS OF:" at 306.259,46.295 h1.52
  text "X" at 296.773,42.828 h1.52
  text "ANSI IPC-A-600F CLASS ->" at 300.303,42.828 h1.52
  text "X" at 341.935,42.828 h1.52
  text "2" at 344.956,42.828 h1.52
  text "1" at 336.955,42.79 h1.52
  text "3" at 353.948,42.79 h1.52
  text "X" at 296.825,38.777 h1.52
  text "UL 94V-0" at 300.303,38.777 h1.52
  text "X" at 317.45,38.777 h1.52
  text "RoHS" at 320.928,38.777 h1.52
  text "OTHER" at 337.296,38.777 h1.52
  text "PER ORDER" at 347.381,38.777 h1.52
  text "ADDITIONAL REQUIREMENTS:" at 287.844,35.195 h1.52
  text "MICROSECTION:" at 289.744,32.274 h1.52
  text "YES" at 312.749,32.274 h1.52
  text "REQUIRED" at 334.631,28.308 h1.52
  text "BARE BOARD ELEC. TEST:" at 289.744,28.236 h1.52
  text "NONE" at 322.909,28.236 h1.52
  text "X" at 331.405,28.236 h1.52
  text "PER ORDER" at 349.668,28.236 h1.52
  text "MANUFACTURER'S UL:" at 289.744,24.248 h1.52
  text "RAIL" at 319.353,24.139 h1.52
  text "METAL" at 331.845,24.139 h1.52
  text "X" at 341.376,24.13 h1.52
  text "SILK" at 344.842,24.139 h1.52
  text ".Layer_Name" at 14.656,-21.806 h1.52
M11 Gerber Information:
  lines w0.254: -7.417,-23.626 160.223,-23.626 ; -7.417,-18.462 160.274,-18.462 ; -7.417,-13.297 -7.417,-28.791 94.31,-28.791 160.274,-28.791 160.274,-13.297 -7.404,-13.297 -7.404,-28.791 32.614,-28.791 ; 55.194,-28.791 55.194,-13.297 ; 87.376,-18.462 87.376,-13.297 ; 108.712,-18.462 108.712,-13.297 ; 124.511,-28.956 124.511,-23.804
  text "ALL ARTWORK VIEWED FROM TOP SIDE" at -5.804,-16.654 h1.52
  text "BOARD #:" at 57.099,-16.654 h1.52
  text ".PRJ_Number" at 70.955,-16.654 h1.52
  text "REV:" at 92.405,-16.654 h1.52
  text ".PCB_Rev" at 99.809,-16.654 h1.52
  text "SVN REV:" at 113.69,-16.654 h1.52
  text ".VersionControl_RevNumber" at 126.543,-16.654 h1.52
  text "LAYER NAME =" at -5.804,-21.806 h1.52
  text "PLOT NAME =" at -5.804,-27.034 h1.52
  text ".plot_File_Name" at 14.656,-27.034 h1.52
  text "GENERATED    :" at 57.15,-27.034 h1.52
  text ".Print_Date" at 79.235,-27.034 h1.52
  text ".Print_Time" at 97.752,-27.034 h1.52
  text "TEXAS INSTRUMENTS" at 129.87,-27.034 h1.52
M12 Stackup:
  lines w0.152: 288.544,189.484 353.314,189.484 ; 288.544,192.136 353.314,192.136 ; 287.02,177.165 ccw(c287.884,177.165) 287.884,176.301 353.974,176.301 ccw(c353.974,177.165) 354.838,177.165 354.838,195.097 ccw(c353.974,195.097) 353.974,195.961 287.884,195.961 ccw(c287.884,195.097) 287.02,195.097 287.02,177.165
  text "The Stackup Legend below this is static." at 294.78,200.012 h1.52
  text "If you change the stackup, update the Legend." at 295.034,197.726 h1.52
  text "Layer Stack Up Detail for: Ref_Design.PcbDoc" at 288.544,192.966 h1.45
  text "Layer" at 288.544,191.145 h0.61
  text "Gerber" at 311.298,191.145 h0.61
  text "Copper" at 325.611,191.145 h0.61
  text "Dielectric" at 340.92,191.145 h0.61
  text "Name" at 288.544,189.926 h0.61
  text "Document" at 311.298,189.926 h0.61
  text "Thickness" at 325.611,189.926 h0.61
  text "Material" at 340.92,189.926 h0.61
  text "Top Solder Mask" at 288.544,187.565 h0.86
  text "(.GTS)" at 311.298,187.565 h0.86
  text "Solder Resist" at 340.92,187.565 h0.86
  text "Top Layer" at 288.544,185.107 h0.86
  text "(.GTL)" at 311.298,185.107 h0.86
  text "1.4mil" at 325.611,185.107 h0.86
  text "FR-4" at 340.92,183.879 h0.86
  text "Bottom Layer" at 288.544,182.65 h0.86
  text "(.GBL)" at 311.298,182.65 h0.86
  text "1.4mil" at 325.611,182.65 h0.86
  text "Bottom Solder Mask" at 288.544,180.192 h0.86
  text "(.GBS)" at 311.298,180.192 h0.86
  text "Solder Resist" at 340.92,180.192 h0.86
  text ".Layer_Name" at 14.656,-21.806 h1.52
M13 Component Bodies Top:
  text ".Layer_Name" at 14.656,-21.806 h1.52
M14 Component Bodies Bottom:
  text ".Layer_Name" at 14.656,-21.806 h1.52
M15 Courtyards Top:
  text ".Layer_Name" at 14.656,-21.806 h1.52
M16 Courtyards Bottom:
  text ".Layer_Name" at 14.656,-21.806 h1.52
Drill Drawing:
  text ".legend" at 130.112,18.428 h1.52
  text "Drill Table" at 130.746,13.729 h1.52
  text ".PRJ_Number" at 39.9,-1.702 h1
  text ".Layer_Name" at 14.656,-21.806 h1.52

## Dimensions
0,0 to -0.3,23.2 on M2 Board Dimensions
0,0 to 33.7,0 on M2 Board Dimensions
